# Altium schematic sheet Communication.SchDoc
size A4
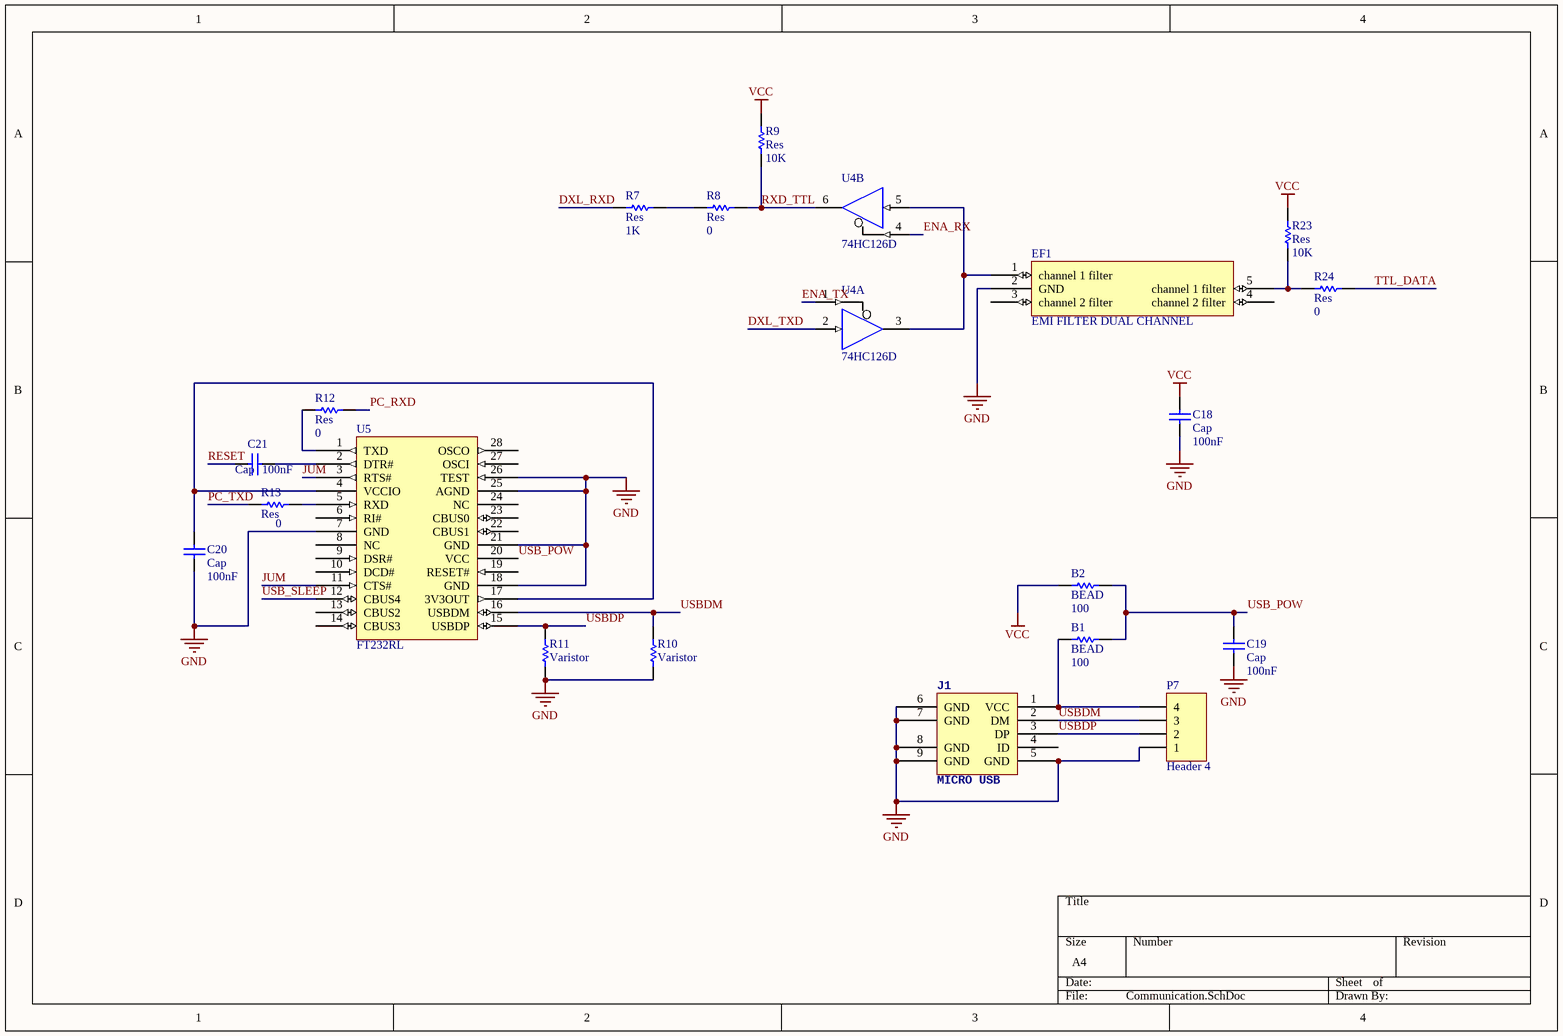
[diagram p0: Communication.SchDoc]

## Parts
B1  BEAD  value 100  [0603-RES]
B2  BEAD  value 100  [0603-RES]
C18  Cap  value 100nF  [0603-CAP]
C19  Cap  value 100nF  [0603-CAP]
C20  Cap  value 100nF  [0603-CAP]
C21  Cap  value 100nF  [0603-CAP]
EF1  EMI FILTER DUAL CHANNEL  [Emi Filter Dual Channel SOTFL]
J1  MICRO USB  [USB_MICRO]
P7  Header 4  [HDR1X4]
R7  Res  value 1K  [0603-RES]
R8  Res  value 0  [0603-RES]
R9  Res  value 10K  [0603-RES]
R10  Varistor  [0603-RES]
R11  Varistor  [0603-RES]
R12  Res  value 0  [0603-RES]
R13  Res  value 0  [0603-RES]
R23  Res  value 10K  [0603-RES]
R24  Res  value 0  [0603-RES]
U4  74HC126D  [14-SOIC]  (parts A,B of 4)
U5  FT232RL  [USB TO SERIAL FT232RL SOP]

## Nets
GND: C18.1 C19.1 C20.1 EF1.2(GND) J1.5(GND) J1.6(GND) J1.7(GND) J1.8(GND) J1.9(GND) P7.1 R10.1 R11.1 U4.7(GND) U5.7(GND) U5.18(GND) U5.21(GND) U5.25(AGND) U5.26(TEST)
VCC: B2.1 C18.2 R9.2 R23.2 U4.14(VCC)
DXL_RXD: R7.1
DXL_TXD: U4.2(A)
ENA_RX: U4.4(OE)
ENA_TX: U4.1(OE)
JUM: U5.3(RTS#) U5.11(CTS#)
PC_RXD: R12.2
PC_TXD: R13.2
RESET: C21.2
RXD_TTL: R8.2 R9.1 U4.6(Y)
TTL_DATA: R24.2
USB_POW: B1.2 B2.2 C19.2 U5.20(VCC)
USB_SLEEP: U5.12(CBUS4)
USBDM: J1.2(DM) P7.3 R10.2 U5.16(USBDM)
USBDP: J1.3(DP) P7.2 R11.2 U5.15(USBDP)
NetB1_1: B1.1 J1.1(VCC) P7.4
NetC20_2: C20.2 U5.4(VCCIO) U5.17(3V3OUT)
NetC21_1: C21.1 U5.2(DTR#)
NetEF1_1: EF1.1(channel_1_filter) U4.3(Y) U4.5(A)
NetEF1_5: EF1.5(channel_1_filter) R23.1 R24.1
NetR7_2: R7.2 R8.1
NetR12_1: R12.1 U5.1(TXD)
NetR13_1: R13.1 U5.5(RXD)

Not connected (* = marked no-connect by the designer): EF1 3(channel_2_filter) 4(channel_2_filter); J1 4(ID); U5 6(RI#) 8(NC) 9(DSR#) 10(DCD#) 13(CBUS2) 14(CBUS3) 19(RESET#) 22(CBUS1) 23(CBUS0) 24(NC) 27(OSCI) 28(OSCO)

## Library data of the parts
B1 B2 R7-R9 R12 R13 R23 R24 = Res: Resistor
C18-C21 = Cap: Capacitor
P7 = Header 4: Header, 4-Pin
R10 R11 = Res: Resistor; Value: 0
U4 = 74HC126D: Quadruple Bus Buffer Gate with 3-State Outputs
